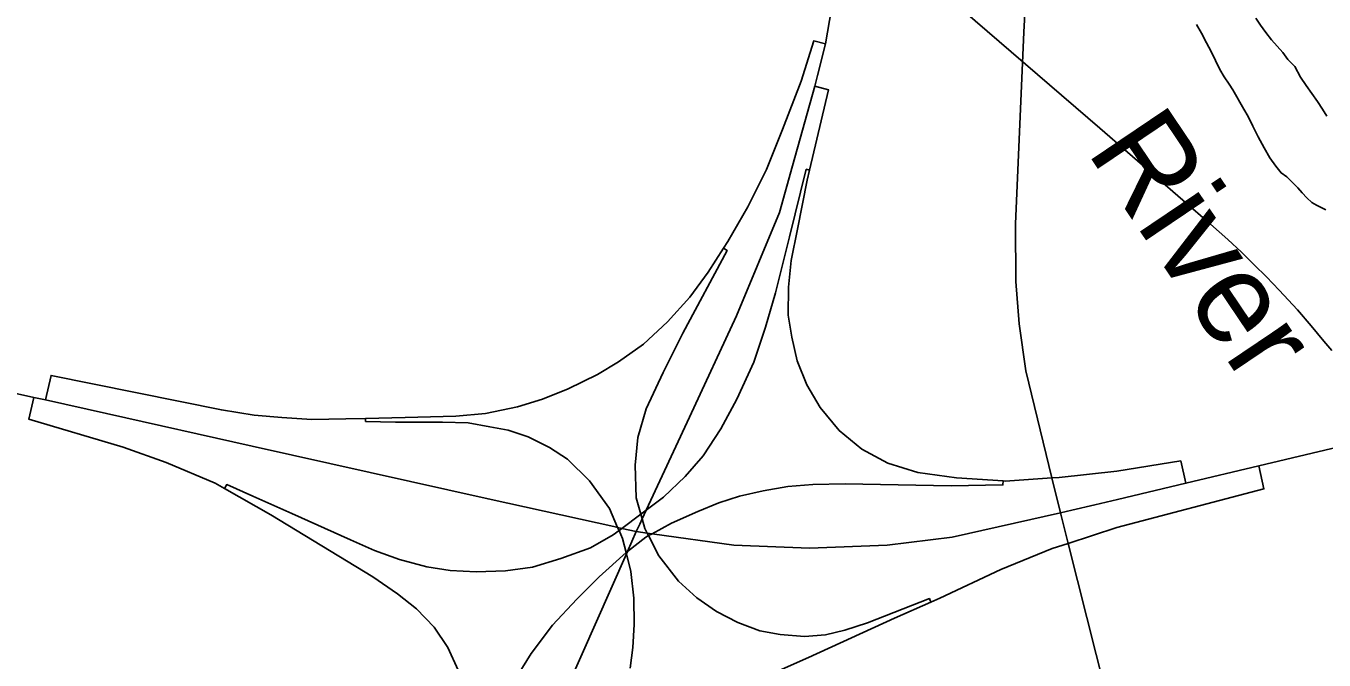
# Model space of a CAD drawing. Extents: x -561 to 1170, y 0 to 846.
# Drawn here: x 270.43 to 285.68, y 197 to 204.45 of the extents above; entities that cross this region are included whole.
import ezdxf

# ---------------------------------------------------------------- set-up
doc = ezdxf.new("R2010")
doc.units = 0
for name, color, linetype in [('GM_X_Interchange_Ramps', 7, 'Continuous'), ('GM_X_Interstate_Route', 7, 'Continuous'), ('GM_X_Major_River', 7, 'Continuous'), ('GM_X_Major_River_Text', 7, 'Continuous'), ('GM_X_Rail_Line', 7, 'Continuous'), ('GM_X_State_Route', 7, 'Continuous')]:
    doc.layers.add(name, color=color, linetype=linetype)

msp = doc.modelspace()

# ---------------------------------------------------------------- linework, layer by layer
at = {"layer": 'GM_X_Interchange_Ramps'}
for points in [[(279.823, 204.238), (279.684, 204.272), (279.536, 203.801), (279.319, 203.234), (279.129, 202.763), (278.909, 202.324), (278.676, 201.917), (278.626, 201.839), (278.445, 201.556), (278.228, 201.263), (277.966, 200.973), (277.684, 200.712), (277.392, 200.504), (277.145, 200.353), (276.8, 200.186), (276.499, 200.065), (276.203, 199.974), (275.829, 199.898), (275.478, 199.863), (274.883, 199.849), (274.417, 199.839), (274.187, 199.834), (273.788, 199.827), (273.435, 199.85), (273.11, 199.876), (272.725, 199.938), (270.724, 200.344), (270.659, 200.055)], [(284.057, 199.077), (283.997, 199.339), (283.246, 199.22), (282.568, 199.144), (282.484, 199.139), (281.935, 199.103), (281.911, 199.104), (281.364, 199.142), (280.908, 199.203), (280.557, 199.312), (280.249, 199.477), (279.983, 199.698), (279.762, 199.965), (279.602, 200.234), (279.491, 200.516), (279.426, 200.793), (279.385, 201.05), (279.39, 201.381), (279.421, 201.694), (279.494, 202.062), (279.606, 202.637), (279.634, 202.756), (279.859, 203.697), (279.696, 203.742)], [(272.76, 199.015), (272.787, 199.061), (273.095, 198.924), (273.553, 198.722), (274.241, 198.414), (274.523, 198.288), (274.818, 198.18), (275.14, 198.094), (275.412, 198.053), (275.72, 198.036), (276.061, 198.05), (276.381, 198.092), (276.713, 198.192), (277.063, 198.32), (277.329, 198.47), (277.397, 198.521), (277.431, 198.547), (277.654, 198.713), (277.717, 198.761), (277.919, 198.912), (278.173, 199.156), (278.387, 199.4), (278.595, 199.715), (278.78, 200.066), (278.979, 200.499), (279.119, 200.912), (279.237, 201.313), (279.398, 201.971), (279.596, 202.765), (279.634, 202.756)], [(278.626, 201.839), (278.667, 201.812), (278.146, 200.838), (277.917, 200.376), (277.717, 199.95), (277.619, 199.615), (277.587, 199.289), (277.6, 198.904), (277.654, 198.713), (277.669, 198.658), (277.701, 198.547), (277.729, 198.492), (277.744, 198.462), (277.865, 198.223), (278.095, 197.925), (278.31, 197.733), (278.542, 197.57), (278.793, 197.44), (279.053, 197.345), (279.291, 197.301), (279.575, 197.275), (279.821, 197.298), (280.05, 197.351), (280.318, 197.438), (281.043, 197.722), (281.061, 197.681)], [(270.52, 200.086), (270.463, 199.828), (271.571, 199.499), (272.077, 199.321), (272.65, 199.078), (272.76, 199.015), (273.304, 198.706), (274.503, 197.976), (274.794, 197.778), (275.017, 197.601), (275.223, 197.388), (275.387, 197.147), (275.506, 196.883)], [(277.527, 196.904), (277.56, 197.149), (277.573, 197.416), (277.57, 197.727), (277.535, 198.041), (277.483, 198.246), (277.479, 198.262), (277.438, 198.427), (277.397, 198.521), (277.38, 198.558), (277.283, 198.782), (277.048, 199.105), (276.792, 199.36), (276.581, 199.497), (276.331, 199.622), (276.093, 199.7), (275.878, 199.741), (275.625, 199.786), (275.324, 199.796), (274.772, 199.793), (274.418, 199.803), (274.417, 199.839)], [(278.271, 196.431), (279.625, 197.03), (280.632, 197.492), (281.061, 197.681), (281.168, 197.728), (281.884, 198.065), (282.486, 198.31), (282.675, 198.371), (283.247, 198.556), (284.975, 199.011), (284.915, 199.281)], [(281.911, 199.104), (281.908, 199.058), (281.298, 199.047), (280.054, 199.069), (279.674, 199.061), (279.38, 199.038), (279.089, 198.987), (278.813, 198.924), (278.569, 198.846), (278.322, 198.745), (278.015, 198.608), (277.785, 198.484), (277.744, 198.462), (277.71, 198.443), (277.497, 198.277), (277.479, 198.262), (277.165, 197.977), (276.901, 197.714), (276.615, 197.41), (276.366, 197.076), (276.161, 196.75)]]:
    msp.add_lwpolyline(points, dxfattribs=at)
at = {"layer": 'GM_X_Interstate_Route'}
for points in [[(279.727, 203.866), (279.823, 204.238), (279.986, 205.201), (280.082, 205.893), (280.148, 206.715), (280.148, 207.857), (280.115, 208.725), (280.081, 208.966)], [(279.435, 202.805), (279.696, 203.742), (279.727, 203.866)], [(278.226, 199.855), (278.778, 201.042), (279.283, 202.257), (279.435, 202.805)], [(262.377, 201.867), (262.389, 201.863), (262.931, 201.73), (268.284, 200.585), (270.52, 200.086), (270.659, 200.055), (271.373, 199.895)], [(284.915, 199.281), (288.659, 200.171)], [(271.373, 199.895), (273.087, 199.513)], [(277.64, 198.596), (277.669, 198.658), (277.717, 198.761), (278.226, 199.855)], [(273.087, 199.513), (275.859, 198.893), (277.372, 198.56)], [(283.254, 198.887), (284.057, 199.077), (284.915, 199.281)], [(277.372, 198.56), (277.38, 198.558), (277.431, 198.547), (277.6, 198.509), (277.729, 198.492), (277.785, 198.484), (278.744, 198.351), (279.633, 198.313), (280.546, 198.348), (281.31, 198.442), (282.584, 198.728), (282.718, 198.759)], [(282.718, 198.759), (282.986, 198.823)], [(282.986, 198.823), (283.254, 198.887)], [(277.132, 197.454), (277.483, 198.246), (277.497, 198.277), (277.6, 198.509), (277.64, 198.596)], [(273.594, 189.421), (273.638, 189.572), (274.366, 191.354), (276.291, 195.554), (276.795, 196.692), (277.132, 197.454)]]:
    msp.add_lwpolyline(points, dxfattribs=at)
at = {"layer": 'GM_X_Major_River'}
for points in [[(285.714, 203.39), (285.664, 203.471), (285.603, 203.562), (285.537, 203.654), (285.471, 203.75), (285.404, 203.847), (285.338, 203.971), (285.255, 204.056), (285.195, 204.137), (285.129, 204.212), (285.063, 204.287), (284.997, 204.373), (284.936, 204.459), (284.881, 204.54)], [(284.881, 204.54), (284.936, 204.459), (284.997, 204.373), (285.063, 204.287), (285.129, 204.212), (285.195, 204.137), (285.255, 204.056), (285.338, 203.971), (285.404, 203.847), (285.471, 203.75), (285.537, 203.654), (285.603, 203.562), (285.664, 203.471), (285.714, 203.39)], [(284.183, 204.466), (284.239, 204.364), (284.3, 204.251), (284.356, 204.149), (284.406, 204.041), (284.456, 203.938)], [(284.456, 203.938), (284.406, 204.041), (284.356, 204.149), (284.3, 204.251), (284.239, 204.364), (284.183, 204.466)], [(284.456, 203.938), (284.506, 203.852), (284.567, 203.766), (284.611, 203.697), (284.738, 203.471), (284.788, 203.384), (284.844, 203.271), (284.905, 203.147), (284.977, 203.018), (285.044, 202.9), (285.116, 202.803), (285.176, 202.723), (285.242, 202.675), (285.286, 202.632), (285.33, 202.589), (285.374, 202.546), (285.423, 202.487), (285.478, 202.428), (285.538, 202.375), (285.593, 202.343), (285.647, 202.317), (285.702, 202.29)], [(285.702, 202.29), (285.647, 202.317), (285.593, 202.343), (285.538, 202.375), (285.478, 202.428), (285.423, 202.487), (285.374, 202.546), (285.33, 202.589), (285.286, 202.632), (285.242, 202.675), (285.176, 202.723), (285.116, 202.803), (285.044, 202.9), (284.977, 203.018), (284.905, 203.147), (284.844, 203.271), (284.788, 203.384), (284.738, 203.471), (284.611, 203.697), (284.567, 203.766), (284.506, 203.852), (284.456, 203.938)]]:
    msp.add_lwpolyline(points, dxfattribs=at)
at = {"layer": 'GM_X_Rail_Line'}
msp.add_lwpolyline([(285.772, 200.636), (285.678, 200.747), (285.531, 200.927), (285.367, 201.113), (285.155, 201.345), (285.003, 201.501), (284.861, 201.642), (284.71, 201.79), (284.55, 201.94), (284.348, 202.12), (283.046, 203.248), (281.132, 204.902)], dxfattribs=at)
at = {"layer": 'GM_X_State_Route'}
for points in [[(282.155, 204.376), (282.161, 204.522), (282.177, 204.881), (282.179, 204.914), (282.194, 205.258), (282.213, 205.69), (282.218, 205.815), (282.216, 206.224), (282.214, 206.252), (282.194, 206.624), (282.046, 207.249), (281.899, 207.676)], [(283.224, 196.198), (282.675, 198.371), (282.584, 198.728), (282.484, 199.139), (282.177, 200.396), (282.099, 200.948), (282.06, 201.446), (282.054, 202.124), (282.155, 204.376)]]:
    msp.add_lwpolyline(points, dxfattribs=at)

# ---------------------------------------------------------------- texts
at = {"layer": 'GM_X_Major_River_Text'}
msp.add_text('River', height=1.0807, rotation=303.9787, dxfattribs=at).set_placement((282.881, 202.98))

doc.saveas('drawing.dxf')
